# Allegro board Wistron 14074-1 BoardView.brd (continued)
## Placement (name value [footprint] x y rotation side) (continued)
PC4917  SC18P50V2JN-1-LL-GP  [C402H22]  141.88 16.32 180 bottom
PC4918  SC4D7U6D3V3KX-GP  [C603H36]  138.76 15.94 180 bottom
PC4919  SC4D7U25V5KX-GP  [C805H54]  140.26 32.66 180 bottom
PC4920  SC4D7U25V5KX-GP  [C805H54]  131.85 36.37 90 bottom
PC4921  SCD1U25V3KX-GP  [C603H36]  135.13 25.07 0 bottom
PC4922  SCD01U50V2KX-1GP  [C402H22]  131.91 39.83 90 bottom
PC4923  SCD01U50V2KX-1GP  [C402H22]  131.85 38.38 90 bottom
PC4924  SC4D7U25V5KX-GP  [C805H54]  142.24 32.66 180 bottom
PC4925  SCD01U50V2KX-1GP  [C402H22]  138.81 32.51 180 bottom
PC4926  SC1U10V2KX-1GP  [C402H22]  141.35 24.77 0 bottom
PC4927  SCD1U25V3KX-GP  [C603H36]  134.89 21.77 90 bottom
PC5001  SC1500P50V3KX-GP  [C603]  90.68 10.54 0 top
PC5002  SCD01U50V2KX-1GP  [C402H22]  71.26 11.73 270 top
PC5003  SCD1U16V2KX-3GP  [C402H22]  72.13 5.71 270 top
PC5004  SCD1U25V3KX-GP  [C603H36]  79.4 9.03 180 top
PC5005  SC1KP50V2KX-1GP  [C402H22]  72.75 11.29 180 top
PC5006  SCD01U16V2KX-3LLGP  [C402H22]  72.25 7.72 270 top
PC5007  SC4D7U25V5KX-GP  [C805H54]  80.59 4.75 270 top
PC5008  SCD22U25V3KX-GP  [C603H40]  71.55 13.57 180 top
PC5009  SC1U16V3KX-2GP  [C603H36]  75.71 13.11 90 top
PC5010  SC1U16V3KX-2GP  [C603H36]  108.56 11.42 180 top
PC5011  SCD1U50V3KX-GP  [C603H36]  90.65 6.62 180 top
PC5012  SC4D7U25V5KX-GP  [C805H54]  80.7 2.79 270 top
PC5028  SC1U10V2KX-1GP  [C402H22]  173.08 26.84 0 top
PC5029  SCD1U16V2KX-3GP  [C402H22]  170.56 28.45 270 bottom
PC5030  SCD033U16V2KX-GP  [C402H22]  177.16 23.6 0 top
PC5031  SC10U6D3V3MX-GP  [C603H38]  176.03 23.97 0 top
PC5032  SCD1U16V2KX-3GP  [C402H22]  181.08 23.85 180 top
PC5033  SC10U6D3V3KX-GP  [C603H38]  174.84 23.97 0 top
PC5034  SC1U10V2KX-1GP  [C402H22]  179.22 32.31 270 top
PC5035  SC1U10V2KX-1GP  [C402H22]  174.22 33.19 180 top
PC5036  SCD1U10V2KX-5GP  [C402H22]  181.86 30.33 90 top
PC5037  SCD1U10V2KX-5GP  [C402H22]  180.61 27.5 0 top
PC5038  SC10U25V5KX-GP  [C805H56]  177.29 34.65 90 top
PC5039  SC10U25V5KX-GP  [C805H56]  177.29 34.67 270 bottom
PC5040  SCD1U50V3KX-GP  [C603H36]  173.33 30.58 270 top
PC5041  SC1KP50V2KX-1GP  [C402H22]  177.64 36.61 0 top
PC5101  SC10U25V5KX-GP  [C805H56]  65.53 113.39 180 bottom
PC5102  SC10U25V5KX-GP  [C805H56]  63.35 112.95 90 top
PC5103  SCD1U16V2KX-3GP  [C402H22]  57.81 101.32 90 bottom
PC5104  SC1U10V2KX-1GP  [C402H22]  70.48 101.09 90 top
PC5105  SCD1U50V3KX-GP  [C603H36]  70.87 103.25 90 top
PC5106  SC1KP50V3KX-GP  [C603H36]  65.28 111.38 270 top
PC5107  SC22P50V2JN-4GP  [C402H22]  61.09 99.8 90 bottom
PC5108  SC10U6D3V3MX-GP  [C603H38]  78.11 101.45 270 top
PC5109  SCD1U16V2KX-3GP  [C402H22]  62.53 98.65 180 bottom
PC5110  SC1U6D3V2KX-GP  [C402H22]  24 85.72 90 top
PC5111  SC1U6D3V2KX-GP  [C402H22]  21.97 85.72 270 top
PC5112  SC1U10V2KX-1GP  [C402H22]  116.46 11.84 90 bottom
PC5211  SCD1U10V2KX-4GP  [C402H20]  90.7 137.79 225 top
PC5212  SCD1U16V2KX-3GP  [C402H22]  97.15 138.35 135 top
PC5213  SC1U10V2KX-1GP  [C402H22]  91.49 138.66 225 top
PC5214  SC10U6D3V3MX-GP  [C603H38]  98.04 137.69 135 top
PC5215  SC22P50V2JN-4GP  [C402H22]  98.25 131.1 315 top
PC5216  SC10U6D3V3MX-GP  [C603H38]  99.51 129.31 315 top
PC5217  SC10U6D3V3MX-GP  [C603H38]  99.57 135.9 135 top
PC5218  SCD1U16V2KX-3GP  [C402H22]  100.11 134.82 135 top
PC5219  SCD1U16V2KX-3GP  [C402H22]  60.99 102.21 90 bottom
PC5220  SCD1U10V2KX-4GP  [C402H20]  51.56 47.88 0 top
PC5221  SCD1U10V2KX-4GP  [C402H20]  90.17 133.93 225 top
PC5222  SCD1U10V2KX-4GP  [C402H20]  25.02 88.14 0 top
PCIE16  PCISLT164-28-GP  [2EG38217-D2D-4F]  16.14 113 90 top
PD5001  RB551V30-GP  [SOD323AKH38]  72.8 3.17 90 top
PG4401  GAP-CLOSE  [CON2C]  112.66 121.65 90 top
PG4402  GAP-CLOSE  [CON2C]  115.74 121.53 270 top
PG4501  GAP-CLOSE  [CON2C]  62.87 72.14 90 top
PG4502  GAP-CLOSE  [CON2C]  65.79 72.14 270 top
PG4901  GAP-CLOSE-PWR-3-GP  [GAP-CLOSE-PWR-3]  140.34 24.77 90 bottom
PG4902  GAP-CLOSE-PWR-3-GP  [GAP-CLOSE-PWR-3]  130.07 9.3 90 top
PG4903  GAP-CLOSE-PWR-3-GP  [GAP-CLOSE-PWR-3]  163.58 28.32 270 top
PG4904  GAP-CLOSE-PWR-3-GP  [GAP-CLOSE-PWR-3]  142.24 24.51 90 bottom
PL4401  IND-D33UH-12-GP-U  [L686647-127318H119]  114.19 121.97 90 top
PL4402  MHC1608S800QBP-GP  [L603H38]  106.05 136.27 0 top
PL4403  MHC1608S800QBP-GP  [L603H38]  106.82 139.32 90 top
PL4501  IND-D33UH-12-GP-U  [L686647-127318H119]  64.27 72.02 90 top
PL4502  MHC1608S800QBP-GP  [L603H38]  36.21 53.47 90 top
PL4601  MHC1608S800QBP-GP  [L603H38]  36.21 54.66 90 top
PL4701  IND-D82UH-19-GP-U  [L686647-127318H119]  90.18 116.58 315 top
PL4702  MHC1608S800QBP-GP  [L603H38]  73.33 130.89 270.3 top
PL4703  MHC1608S800QBP-GP  [L603H38]  83.95 131.32 135 top
PL4801  MHC1608S800QBP-GP  [L603H38]  168.15 33.51 0 top
PL4901  MHC1608S800QBP-GP  [L603H38]  140.26 36.24 180 bottom
PL4902  MHC1608S800QBP-GP  [L603H38]  142.24 36.24 180 bottom
PL4903  IND-3D3UH-116-GP-U  [L686647-127318H119]  129.39 25.77 0 bottom
PL4904  IND-3D3UH-116-GP-U  [L686647-127318H119]  152.91 30.1 270 bottom
PL5001  IND-D82UH-19-GP-U  [L686647-127318H119]  178.16 48.25 180 top
PL5002  MHC1608S800QBP-GP  [L603H38]  170.65 33.46 0 top
PL5003  MHC1608S800QBP-GP  [L603H38]  171.84 33.46 0 top
PL5004  MHC1608S800QBP-GP  [L603H38]  81.81 7.37 0 top
PL5005  IND-5D6UH-45-GP-U  [L686647-127318H119]  101.63 6.86 90 top
PL5006  MHC1608S800QBP-GP  [L603H38]  62.87 116.37 180 top
PL5007  MHC1608S800QBP-GP  [L603H38]  80.64 7.37 0 top
PL5101  IND-2D2UH-122-GP-U  [L686647-127318H119]  74.98 113.67 90 top
PL5102  MHC1608S800QBP-GP  [L603H38]  64.03 116.36 180 top
PL5103  MHC1608S800QBP-GP  [L603H38]  73.37 130.89 90 bottom
PN4401  NTC-100K-20-GP  [NTC-402H24-U]  120.4 131.14 180 top
PN4402  NTC-100K-20-GP  [NTC-402H24-U]  119.33 124.13 0 top
PN4501  NTC-100K-20-GP  [NTC-402H24-U]  51.69 78.11 90 top
PN4502  NTC-100K-20-GP  [NTC-402H24-U]  63.53 76.53 90 top
PQ4401  AON6520-GP  [PPAK-8P-5262H40]  107.81 130.87 0 top
PQ4402  AON6510-GP  [PPAK-8P-5262H40]  116.51 129.21 180 top
PQ4501  AON6520-GP  [PPAK-8P-5262H40]  54.61 65.7 90 top
PQ4502  AON6510-GP  [PPAK-8P-5262H40]  56.48 74.21 270 top
PQ4701  AON6520-GP  [PPAK-8P-5262H40]  87.48 126.4 45 top
PQ4702  AON6510-GP  [PPAK-8P-5262H40]  84.09 120.5 225 top
PQ4901  SM3319NSQGC-TRG-GP  [PPAK-8P-3030H40]  145.13 34.8 270 bottom
PQ4902  SM3317NSQGC-TRG-GP  [PPAK-8P-3030H40]  146.44 27.58 90 bottom
PQ4903  SM3319NSQGC-TRG-GP  [PPAK-8P-3030H40]  135.48 33.55 180 bottom
PQ4904  SM3317NSQGC-TRG-GP  [PPAK-8P-3030H40]  128.37 32.16 0 bottom
PQ5001  AON6520-GP  [PPAK-8P-5262H40]  173.38 38.82 180 top
PQ5002  AON6510-GP  [PPAK-8P-5262H40]  181.9 40.55 0 top
PQ5003  SM3319NSQGC-TRG-GP  [PPAK-8P-3030H40]  93.85 3.94 90 top
PQ5004  SM3317NSQGC-TRG-GP  [PPAK-8P-3030H40]  95.25 8.61 270 top
PQ5005  2N7002KDW-1-GP  [SOT-363H44]  80.49 16.21 270 top
PQ5101  SM3319NSQAC-TRG-GP  [PPAK-8P-3232H40]  67.05 115.24 90 top
PQ5102  SM3319NSQAC-TRG-GP  [PPAK-8P-3232H40]  68.47 108.54 270 top
PR3601  124R2F-U-GP  [R402H16]  119.91 11.84 90 bottom
PR3602  210R2F-L-GP  [R402H16]  115.37 12.88 90 bottom
PR4201  30KR2F-GP  [R402H16]  186.31 80.19 90 bottom
PR4202  390R2F-2GP  [R402H16]  189.38 91.67 0 bottom
PR4203  8K2R2F-1-GP  [R402H16]  188.34 91.72 0 bottom
PR4204  300KR2F-GP  [R402H16]  186.31 81.23 90 bottom
PR4205  30KR2F-GP  [R402H16]  190.88 90.07 90 bottom
PR4206  300KR2F-GP  [R402H16]  190.93 91.19 90 bottom
PR4207  15KR2F-GP  [R402H16]  188.72 93.22 90 bottom
PR4208  15KR2F-GP  [R402H16]  182.32 91.87 0 bottom
PR4209  100KR2F-L1-GP  [R402H16]  180.42 86.28 270 bottom
PR4210  15KR2F-GP  [R402H16]  182.78 93.34 270 bottom
PR4211  20KR2J-L2-GP  [R402H16]  190.47 80.04 0 bottom
PR4212  20KR2J-L2-GP  [R402H16]  189.41 80.04 0 bottom
PR4213  100KR2F-L1-GP  [R402H16]  180.39 87.33 90 bottom
PR4214  200KR2F-L-GP  [R402H16]  187.81 151.16 180 top
PR4215  100KR2J-1-GP  [R402H16]  187.37 149.58 270 top
PR4216  0R2J-2-GP  [R402H16]  190.88 92.23 90 bottom
PR4217  D1R2512F-3-GP-U  [R2512-1U1H36]  185.57 76.21 90 bottom
PR4218  300KR2F-GP  [R402H16]  184.4 81.23 90 bottom
PR4219  30KR2F-GP  [R402H16]  184.4 79.3 270 bottom
PR4220  0R5J-5-GP  [R805H24]  188.47 71.72 180 bottom
PR4221  0R5J-5-GP  [R805H24]  190.42 71.7 180 bottom
PR4222  0R2J-2-GP  [R402H16]  184.78 92.33 90 bottom
PR4223  15KR2F-GP  [R402H16]  186.82 93.24 270 bottom
PR4224  0R5J-5-GP  [R805H24]  192.38 71.7 180 bottom
PR4225  0R0402-PAD-2-GP  [0R0402-PAD-1]  184.78 91.26 90 bottom
PR4226  0R5J-5-GP  [R805H24]  194.36 71.7 180 bottom
PR4401  1KR2J-1-GP  [R402H16]  128.04 138.76 270 top
PR4404  47R2F-GP  [R402H16]  137.29 132.08 90 bottom
PR4405  1KR2F-3-GP  [R402H16]  136.88 131.85 180 top
PR4406  560KR2F-GP  [R402H16]  139.04 131.85 180 top
PR4407  3K3R2F-2-GP  [R402H16]  138.4 130.2 270 top
PR4408  100R2J-2-GP  [R402H14]  140.44 134.87 180 bottom
PR4409  100R2J-2-GP  [R402H14]  140.46 133.35 270 top
PR4410  0R0402-PAD-2-GP  [0R0402-PAD-1]  138.53 135.51 90 top
PR4411  1K5R2F-2-GP  [R402H16]  138.53 134.37 90 top
PR4413  0R0402-PAD-2-GP  [0R0402-PAD-1]  126.9 132.61 270 top
PR4414  62KR2F-GP  [R402H16]  125.45 132.18 0 top
PR4415  34KR2F-GP  [R402H16]  131.83 130.43 0 bottom
PR4416  10R2J-2-GP  [R402H14]  129.29 127.38 180 top
PR4417  100KR3F-GP  [R603H22]  130.43 126.85 180 top
PR4418  4K7R2F-GP  [R402H16]  137.16 128.22 270 top
PR4419  75KR2F-GP  [R402H16]  134.32 127.81 90 top
PR4420  150KR2F-L-GP  [R402H16]  132.74 127.25 180 top
PR4421  2D2R5J-1-GP  [R805H24]  112.19 127.81 180 top
PR4422  10KR2J-3-GP  [R402H16]  112.14 128.02 180 bottom
PR4423  0R5J-5-GP  [R805H24]  112.14 130.81 0 bottom
PR4424  2D2R5J-1-GP  [R805H24]  126.47 135.25 90 top
PR4426  54D9R2F-L1-GP  [R402H16]  131.29 138.68 270 top
PR4427  75R2F-2-GP  [R402H16]  131.93 137.16 0 top
PR4428  1R3J-L1-GP  [R603H22]  124.59 129.64 90 top
PR4429  1KR2J-1-GP  [R402H16]  125.6 137.24 0 top
PR4430  2D2R5J-1-GP  [R805H24]  138.91 138.43 270 top
PR4431  0R2J-2-GP  [R402H16]  125.55 130.73 270 top
PR4432  22KR2F-GP  [R402H16]  127.36 127.38 0 top
PR4433  18K7R2F-GP  [R402H16]  134.24 131.06 90 bottom
PR4434  1KR2J-1-GP  [R402H16]  125.6 137.16 180 bottom
PR4501  1KR2J-1-GP  [R402H16]  41.61 70.08 180 top
PR4504  47R2F-GP  [R402H16]  33.71 74.8 90 top
PR4505  1KR2F-3-GP  [R402H16]  33.71 75.84 90 top
PR4506  560KR2F-GP  [R402H16]  33.15 78.23 0 bottom
PR4507  3K3R2F-2-GP  [R402H16]  33.2 78.26 0 top
PR4510  0R0402-PAD-2-GP  [0R0402-PAD-1]  33.32 70.92 90 top
PR4511  1K5R2F-2-GP  [R402H16]  33.71 72.87 270 top
PR4513  0R0402-PAD-2-GP  [0R0402-PAD-1]  43.69 78.23 90 top
PR4514  62KR2F-GP  [R402H16]  45.59 78.23 90 top
PR4515  30KR2F-GP  [R402H16]  37.39 79.71 90 top
PR4516  10R2J-2-GP  [R402H14]  40.18 81.31 0 top
PR4517  100KR3F-GP  [R603H22]  40.18 83.59 0 top
PR4518  10KR2F-2-GP  [R402H16]  36.7 81.28 270 top
PR4519  75KR2F-GP  [R402H16]  38 82.93 0 top
PR4520  150KR2F-L-GP  [R402H16]  39.04 82.93 180 top
PR4521  2D2R5J-1-GP  [R805H24]  56.91 69.98 270 top
PR4522  10KR2J-3-GP  [R402H16]  46.1 75.82 0 top
PR4523  0R5J-5-GP  [R805H24]  43.81 74.4 270 top
PR4524  2D2R5J-1-GP  [R805H24]  43.84 72.34 270 top
PR4526  54D9R2F-L1-GP  [R402H16]  38.99 69.39 90 top
PR4527  75R2F-2-GP  [R402H16]  39.42 70.87 180 top
PR4528  1R3J-L1-GP  [R603H22]  44.75 82.58 0 top
PR4529  1KR2J-1-GP  [R402H16]  42.6 69.95 0 bottom
PR4530  2D2R5J-1-GP  [R805H24]  35.59 70.55 180 top
PR4531  48D7KR2F-GP  [R402H16]  43.69 79.38 90 top
PR4532  53K6R2F-GP  [R402H16]  42.29 81.28 180 top
PR4533  18K7R2F-GP  [R402H16]  33.66 79.76 270 top
PR4601  1KR2J-1-GP  [R402H16]  44.2 70.74 270 top
PR4701  5D1R2J-1-GP  [R402H16]  68.73 120.85 180 top
PR4702  470KR2F-GP  [R402H16]  69.47 124.71 0 top
PR4706  0R0603-PAD-2-GP-U  [0R0603-PAD-1-U]  94.33 113.28 45 top
PR4711  68KR2F-GP  [R402H16]  70.96 130.12 180 top
PR4712  2K2R2J-2-GP  [R402H16]  75.41 126.24 270 top
PR4713  2D2R5J-1-GP  [R805H24]  85.84 125.35 45 bottom
PR4714  2D2R5J-1-GP  [R805H24]  75.23 121.18 180 top
PR4715  10KR2J-3-GP  [R402H16]  92.18 123.39 135 top
PR4716  2D2R5J-1-GP  [R805H24]  93.84 121.81 45 top
PR4717  5K11R2F-L1-GP  [R402H16]  67.93 125.27 90 top
PR4718  10KR2F-2-GP  [R402H16]  67.94 126.31 270 top
PR4720  3K3R2J-3-GP  [R402H16]  59.46 100.99 0 bottom
PR4801  0R0805-PAD-2-GP-U  [0R0805-PAD-1-U]  49.35 54.64 270 top
PR4802  0R0603-PAD-2-GP-U  [0R0603-PAD-1-U]  49.07 52.93 270 top
PR4803  10KR2F-2-GP  [R402H16]  60.66 50.98 0 top
PR4804  0R0805-PAD-2-GP-U  [0R0805-PAD-1-U]  61.09 56.57 180 top
PR4805  2K2R2J-2-GP  [R402H16]  48.67 51.21 0 top
PR4806  4K42R2F-GP  [R402H16]  60.66 53.01 0 top
PR4820  3K3R2J-3-GP  [R402H16]  49.12 48.77 90 top
PR4903  2D2R5J-1-GP  [R805H24]  145.26 19.41 270 bottom
PR4904  0R5J-5-GP  [R805H24]  134.75 32.51 0 top
PR4905  0R5J-5-GP  [R805H24]  145.92 32.38 0 top
PR4906  0R0805-PAD-2-GP-U  [0R0805-PAD-1-U]  124.28 10.74 90 top
PR4907  0R0805-PAD-2-GP-U  [0R0805-PAD-1-U]  160.05 24.92 270 bottom
PR4908  0R0805-PAD-2-GP-U  [0R0805-PAD-1-U]  124.28 8.81 90 top
PR4909  0R0805-PAD-2-GP-U  [0R0805-PAD-1-U]  160.07 30.89 270 bottom
PR4910  0R0805-PAD-2-GP-U  [0R0805-PAD-1-U]  124.28 6.88 90 top
PR4911  2D2R5J-1-GP  [R805H24]  131.8 32.34 0 bottom
PR4912  2D2R5J-1-GP  [R805H24]  146.25 31.55 90 bottom
PR4913  0R0805-PAD-2-GP-U  [0R0805-PAD-1-U]  160.07 26.9 270 bottom
PR4914  6K65R2F-GP  [R402H16]  136.65 16.33 0 bottom
PR4915  0R0805-PAD-2-GP-U  [0R0805-PAD-1-U]  160.07 28.91 270 bottom
PR4916  10KR2F-2-GP  [R402H16]  137.67 16.33 180 bottom
PR4917  21K5R2F-GP  [R402H16]  139.27 24.74 180 bottom
PR4918  68KR2F-GP  [R402H16]  140.89 16.33 180 bottom
PR4919  10KR2F-2-GP  [R402H16]  138.25 24.77 0 bottom
PR4920  15KR2F-GP  [R402H16]  144.96 17.43 0 bottom
PR4921  10KR2F-2-GP  [R402H16]  144.43 15.93 270 bottom
PR4922  100KR2J-1-GP  [R402H16]  135.54 18.62 270 bottom
PR4923  127KR2F-GP  [R402H16]  139.85 16.33 180 bottom
PR4924  130KR2F-GP  [R402H16]  142.85 16.3 180 bottom
PR4925  100KR2J-1-GP  [R402H16]  136.78 24.26 270 bottom
PR4926  2D2R5J-1-GP  [R805H24]  134.42 20.14 270 bottom
PR5001  2D2R5J-1-GP  [R805H24]  94.54 8.1 270 bottom
PR5002  16KR2F-GP  [R402H16]  79.25 11.38 180 top
PR5003  3K3R2F-2-GP  [R402H16]  72.69 13.21 180 top
PR5004  75R2F-2-GP  [R402H16]  69.77 11.23 180 top
PR5005  2K21R2F-GP  [R402H16]  71.25 10.79 90 top
PR5006  158R2F-GP  [R402H16]  72.31 9.73 270 top
PR5007  0R0805-PAD-2-GP-U  [0R0805-PAD-1-U]  114.07 11.53 180 top
PR5008  0R0805-PAD-2-GP-U  [0R0805-PAD-1-U]  112.12 11.53 180 top
PR5009  0R0805-PAD-2-GP-U  [0R0805-PAD-1-U]  110.16 11.53 180 top
PR5010  2D2R5J-1-GP  [R805H24]  76.99 4.72 90 top
PR5011  2D2R5J-1-GP  [R805H24]  93.8 11.79 270 top
PR5012  10KR2F-2-GP  [R402H16]  182.09 23.85 0 top
PR5013  2D2R5J-1-GP  [R805H24]  76.15 14.68 270 top
PR5014  4D7R5J-1-GP  [R805H24]  77.01 6.71 270 top
PR5015  10KR2J-3-GP  [R402H16]  72.11 4.75 90 top
PR5016  10KR2J-3-GP  [R402H16]  96.9 8.77 0 bottom
PR5017  158R2F-GP  [R402H16]  72.31 8.66 270 top
PR5018  2K21R2F-GP  [R402H16]  72.06 6.73 270 top
PR5023  8K87R2F-2-GP  [R402H16]  177.29 33.15 270 top
PR5024  5D1R2J-1-GP  [R402H16]  177.3 32.13 90 top
PR5025  0R0805-PAD-2-GP-U  [0R0805-PAD-1-U]  160.39 51.7 270 top
PR5026  0R0805-PAD-2-GP-U  [0R0805-PAD-1-U]  160.39 49.76 270 top
PR5027  0R0603-PAD-2-GP-U  [0R0603-PAD-1-U]  172.39 25.12 90 top
PR5028  0R0805-PAD-2-GP-U  [0R0805-PAD-1-U]  160.37 47.8 270 top
PR5029  2D2R5J-1-GP  [R805H24]  177.66 40.59 0 top
PR5030  2D2R3J-2-GP  [R603H22]  172.42 29.09 90 top
PR5031  620KR2F-GP  [R402H16]  181.89 31.32 270 top
PR5032  100KR2J-1-GP  [R402H16]  182.07 32.36 270 top
PR5033  0R0805-PAD-2-GP-U  [0R0805-PAD-1-U]  160.36 43.9 270 top
PR5034  0R0603-PAD-2-GP-U  [0R0603-PAD-1-U]  170.4 26.67 90 bottom
PR5035  0R0402-PAD-2-GP  [0R0402-PAD-1]  179 23.87 0 top
PR5036  0R0805-PAD-2-GP-U  [0R0805-PAD-1-U]  160.36 45.86 270 top
PR5037  2D2R5J-1-GP  [R805H24]  171.3 39.02 180 bottom
PR5038  0R0805-PAD-2-GP-U  [0R0805-PAD-1-U]  160.36 41.95 270 top
PR5041  8K06R2F-GP  [R402H16]  180.06 23.85 180 top
PR5101  15K8R2F-GP  [R402H16]  61.1 98.84 90 bottom
PR5102  10KR2F-2-GP  [R402H16]  61.1 97.82 270 bottom
PR5103  10KR2J-3-GP  [R402H16]  70.1 116.26 90 bottom
PR5104  5D1R2J-1-GP  [R402H16]  70.48 102.11 270 top
PR5105  2D2R5J-1-GP  [R805H24]  68.44 111.83 270 top
PR5106  2D2R5J-1-GP  [R805H24]  71.25 104.9 270 top
PR5107  196KR2F-GP  [R402H16]  60.99 103.23 90 bottom
PR5108  0R0603-PAD-2-GP-U  [0R0603-PAD-1-U]  23.7 83.91 180 top
PR5109  0R0603-PAD-2-GP-U  [0R0603-PAD-1-U]  22.3 83.78 0 top
PR5110  100KR2F-L1-GP  [R402H16]  25.02 90.68 180 top
PR5115  2K2R2J-2-GP  [R402H16]  57.76 100.23 90 bottom
PR5116  470KR2F-GP  [R402H16]  65.38 100.05 270 bottom
PR5117  2D2R5J-1-GP  [R805H24]  66.98 118.47 270 top
PR5120  3K3R2J-3-GP  [R402H16]  57.81 102.34 90 bottom
PR5209  0R0603-PAD-2-GP-U  [0R0603-PAD-1-U]  92.07 139.76 225 top
PR5210  0R0805-PAD-2-GP-U  [0R0805-PAD-1-U]  96.23 139.82 135 top
PR5211  10KR2F-2-GP  [R402H16]  96.77 129.69 315 top
PR5213  0R0805-PAD-2-GP-U  [0R0805-PAD-1-U]  101.37 130.81 45 top
PR5214  5K49R2F-GP  [R402H16]  98.97 130.38 315 top
PR5215  0R0603-PAD-2-GP-U  [0R0603-PAD-1-U]  87.43 106.38 45 top
PR5216  0R0603-PAD-2-GP-U  [0R0603-PAD-1-U]  88.41 107.35 45 top
PR5217  0R0603-PAD-2-GP-U  [0R0603-PAD-1-U]  89.39 108.34 45 top
PR5218  0R0603-PAD-2-GP-U  [0R0603-PAD-1-U]  90.38 109.33 45 top
PR5219  0R0603-PAD-2-GP-U  [0R0603-PAD-1-U]  91.37 110.32 45 top
PR5220  0R0603-PAD-2-GP-U  [0R0603-PAD-1-U]  92.36 111.31 45 top
PR5221  0R0603-PAD-2-GP-U  [0R0603-PAD-1-U]  93.34 112.29 45 top
PR5222  0R0603-PAD-2-GP-U  [0R0603-PAD-1-U]  84.05 105.4 45 top
PR5223  0R0603-PAD-2-GP-U  [0R0603-PAD-1-U]  83.06 104.42 45 top
PR5224  0R0603-PAD-2-GP-U  [0R0603-PAD-1-U]  81.09 102.44 45 top
PR5225  0R0603-PAD-2-GP-U  [0R0603-PAD-1-U]  82.08 103.43 45 top
PR5229  10KR2J-3-GP  [R402H16]  57.99 48.64 270 top
PR5231  2K2R2J-2-GP  [R402H16]  89.99 137.07 45 top
PR5232  10KR2J-3-GP  [R402H16]  182.63 26.85 180 top
PR5233  10KR2J-3-GP  [R402H16]  181.86 29.34 270 top
PR5234  10KR2J-3-GP  [R402H16]  181.99 28.3 270 top
PR5240  3K3R2J-3-GP  [R402H16]  89.2 136.32 225 top
PR9742  0R0402-PAD-2-GP  [0R0402-PAD-1]  134.21 139.45 180 top
PR9757  0R0402-PAD-2-GP  [0R0402-PAD-1]  134.34 137.41 0 top
PR9758  200R2J-L1-GP  [R402H16]  133.07 137.16 180 top
PR9759  200R2J-L1-GP  [R402H16]  38.4 70.87 0 top
PR9763  10KR2J-3-GP  [R402H16]  181.61 26.82 180 top
PR9764  100R2J-2-GP  [R402H14]  33.3 70.94 90 bottom
PR9765  100R2J-2-GP  [R402H14]  33.22 73.25 0 bottom
PR9766  100R2J-2-GP  [R402H14]  94.78 81.64 270 bottom
PT4401  E820U2D5VM-6-GP  [ECAP-100D6D3H375]  123.83 123.95 0 top
PT4402  E820U2D5VM-6-GP  [ECAP-100D6D3H375]  122.5 116.23 0 top
PT4403  E820U2D5VM-6-GP  [ECAP-100D6D3H375]  129.9 118.99 0 top
PT4491  E270U16VM-16-GP  [ECAP-138D8-UH355]  118.75 139.95 0 top
PT4501  E820U2D5VM-6-GP  [ECAP-100D6D3H375]  81.25 81.13 90 top
PT4502  E820U2D5VM-6-GP  [ECAP-100D6D3H375]  72.54 76.99 0 top
PT4503  E820U2D5VM-6-GP  [ECAP-100D6D3H375]  72.75 69.11 0 top
PT4504  E820U2D5VM-6-GP  [ECAP-100D6D3H375]  79.55 73.46 0 top
PT4591  E270U16VM-16-GP  [ECAP-138D8-UH355]  42.42 52.98 0 top
PT4701  E820U2D5VM-6-GP  [ECAP-100D6D3H375]  83.52 111.28 90 top
PT4702  E560U6D3VM-3-GP  [ECAP-100D6D3H375]  78.59 130.3 0 top
PT4901  ST15U25VDM-7-GP  [CT7343H83]  139.7 32.03 0 top
PT4902  SE220U6D3VM-30-GP  [SE361416H178]  130.05 8.64 0 top
PT4903  SE220U6D3VM-30-GP  [SE361416H178]  163.55 27.67 0 top
PT5001  E820U2D5VM-6-GP  [ECAP-100D6D3H375]  170.43 50.4 90 top
PT5002  E820U2D5VM-6-GP  [ECAP-100D6D3H375]  166.13 43.85 90 top
PT5003  E560U6D3VM-3-GP  [ECAP-100D6D3H375]  163.9 36.34 0 top
PT5004  SE47U25VM-13-GP  [SE361414H241]  86.23 8.51 180 top
PT5005  E100U16VM-108-GP-U  [ECAP-100D6D3H237]  110.14 5.82 90 top
PT5101  E560U6D3VM-3-GP  [ECAP-100D6D3H375]  60.48 108.05 89.7 top
PT5102  E820U2D5VM-6-GP  [ECAP-100D6D3H375]  77.04 105.97 90 top
PU3601  UZ1085G-ADJ-TN3-R-1-GP-U  [SMD-TO-252-4H100]  118.11 16.18 90 bottom
PU4201  AO4407AL-GP  [SOIC8H69]  193.12 148.59 180 top
PU4202  LM358DR2G-GP  [SOIC8H69]  184.45 85.42 0 bottom
PU4203  LM358DR2G-GP  [SOIC8H69]  190.12 85.37 0 bottom
PU4401  NCP81201MNTXG-GP-U2  [LFQFN28J4-G2D7-UH40]  132.44 131.84 0 top
PU4501  NCP81201MNTXG-GP-U2  [LFQFN28J4-G2D7-UH40]  38.53 75.32 180 top
PU4701  RT8237CZQW-2-GP  [DFN10G3-G265175H32]  72.24 125.37 0 top
PU4801  APL5930KAI-TRG-1-GP  [SOIC8-G3530H63]  55.07 52.19 90 top
PU4902  RT8243BZQW-GP  [QFN20-G1D75H32]  139.85 20.53 0 bottom
PU5001  NCP1589AMNTWG-GP-U2  [LFDFN10G3-G2619H40]  75.78 10.26 270 top
PU5004  RT8207MZQW-GP-U  [QFN20-G1D75H32]  177.21 28.36 180 top
PU5101  RT8237CZQW-2-GP  [DFN10G3-G265175H32]  65.91 102.74 90 top
PU5102  S-1339D15-M5001-GP  [SOT-23-5H52]  22.61 91.44 0 top
PU5202  APL5930KAI-TRG-1-GP  [SOIC8-G3530H63]  94.96 134.23 45 top
Q1906  LMBT3904LT1G-GP  [SOT23CBE2D4H44]  33.66 137.87 180 top
Q2001  2N7002H-GP  [SOT23DGS2D4H44]  92.44 24.81 180 bottom
Q2501  MMBT3906-4-GP  [SOT23CBE2D4H44]  187.66 40.01 180 top
Q2502  MMBT3906-4-GP  [SOT23CBE2D4H44]  185.57 45.82 270 top
Q2503  LMBT3904LT1G-GP  [SOT23CBE2D4H44]  185.6 50.44 90 top
Q2701  MMDT3904-7-F-1-GP  [SOT-363H44]  33.3 151.23 270 top
Q2702  MMDT3904-7-F-1-GP  [SOT-363H44]  16.86 138.05 180 bottom
Q2703  MMDT3904-7-F-1-GP  [SOT-363H44]  16.82 134 0 bottom
Q2704  MMDT3904-7-F-1-GP  [SOT-363H44]  50.57 141.76 270 top
Q2705  MMDT3904-7-F-1-GP  [SOT-363H44]  42.9 142.78 270 top
Q2706  MMBT3906-4-GP  [SOT23CBE2D4H44]  26.34 139.73 270 top
Q2707  MMBT3906-4-GP  [SOT23CBE2D4H44]  16.87 144.41 90 top
Q2709  MMBT3906-4-GP  [SOT23CBE2D4H44]  24.43 144.42 270 top
Q2711  MMBT3904-4-GP  [SOT23CBE2D4H44]  37.54 115.11 90 bottom
Q2712  MMBT3904-4-GP  [SOT23CBE2D4H44]  20.65 144.41 90 top
Q3401  MMBT3906-4-GP  [SOT23CBE2D4H44]  12.37 18.49 0 bottom
Q3402  MMBT3904-4-GP  [SOT23CBE2D4H44]  177.77 18.67 90 bottom
Q3403  2N7002H-GP  [SOT23DGS2D4H44]  8.69 31.11 180 bottom
Q3404  MMBT3906-4-GP  [SOT23CBE2D4H44]  12.45 31.06 0 bottom
Q3409  2N7002KDW-1-GP  [SOT-363H44]  7.57 12.78 270 top
Q3507  QM3004D-GP  [SMD-TO-252-DGS6698H99]  191.26 22.71 180 top
Q3508  AO3413L-GP  [SOT23DGS2D8H50]  181.86 15.19 180 top
Q3509  AO3413L-GP  [SOT23DGS2D8H50]  184.23 19 270 top
Q3510  AO3413L-GP  [SOT23DGS2D8H50]  6.63 98.15 90 bottom
Q3511  AO3413L-GP  [SOT23DGS2D8H50]  6.63 102.34 90 bottom
Q3512  2N7002H-GP  [SOT23DGS2D4H44]  160.53 19.18 0 bottom
Q3514  2N7002H-GP  [SOT23DGS2D4H44]  156.97 18.34 180 bottom
Q3516  2N7002H-GP  [SOT23DGS2D4H44]  156.84 22.05 90 bottom
Q4001  2N7002KDW-1-GP  [SOT-363H44]  99.3 36.63 180 bottom
Q4101  2N7002KDW-1-GP  [SOT-363H44]  6.55 17.07 90 bottom
Q4201  2N7002A-7-GP  [SOT23DGS2D4H48]  179.86 79.28 0 bottom
Q4202  2N7002KDW-GP  [SOT-363H44]  179.96 83.95 180 bottom
Q4301  MMBT3906-4-GP  [SOT23CBE2D4H44]  171.93 17.91 0 bottom
Q4302  2N7002KDW-GP  [SOT-363H44]  179.07 89.66 0 bottom
Q4303  2N7002KDW-1-GP  [SOT-363H44]  151.43 22.05 180 bottom
Q4304  2N7002H-GP  [SOT23DGS2D4H44]  179.87 75.51 180 bottom
Q5401  2N7002A-7-GP  [SOT23DGS2D4H48]  164.34 20.24 0 bottom
Q6502  2N7002H-GP  [SOT23DGS2D4H44]  158.19 157.15 0 top
Q6503  2N7002H-GP  [SOT23DGS2D4H44]  135.31 154.13 270 top
Q6504  LMBT3904LT1G-GP  [SOT23CBE2D4H44]  16.33 23.72 90 bottom
Q6509  DMN5L06K-7-GP  [SOT23DGS2D4H48]  174.24 77.34 180 bottom
Q6510  2N7002H-GP  [SOT23DGS2D4H44]  175.4 64.75 90 bottom
Q6511  DMN5L06K-7-GP  [SOT23DGS2D4H48]  174.24 73.53 0 bottom
Q6512  2N7002H-GP  [SOT23DGS2D4H44]  174.24 69.6 180 bottom
Q6514  2N7002H-GP  [SOT23DGS2D4H44]  157.61 144.53 90 top
Q6515  DMN5L06K-7-GP  [SOT23DGS2D4H48]  155.45 150.75 90 top
Q6516  DMN5L06K-7-GP  [SOT23DGS2D4H48]  160.12 153.34 0 top
Q6517  DMN5L06K-7-GP  [SOT23DGS2D4H48]  127.44 149.96 180 top
Q6518  DMN5L06K-7-GP  [SOT23DGS2D4H48]  131.52 152.46 270 top
Q6519  2N7002H-GP  [SOT23DGS2D4H44]  131.11 148.77 180 top
Q6520  2N7002H-GP  [SOT23DGS2D4H44]  181.1 141.35 90 top
Q6527  2N7002H-GP  [SOT23DGS2D4H44]  7.32 90.42 180 bottom
Q6528  2N7002KDW-1-GP  [SOT-363H44]  63.39 125.11 180 bottom
Q6530  MMDT3904-7-F-1-GP  [SOT-363H44]  5.71 64.52 0 bottom
Q6531  MMDT3904-7-F-1-GP  [SOT-363H44]  6.1 54.53 0 bottom
Q6532  LMBT3904LT1G-GP  [SOT23CBE2D4H44]  184.12 66.9 180 bottom
Q6533  MMDT3904-7-F-1-GP  [SOT-363H44]  187.43 66.9 0 bottom
Q6539  LMBT3904LT1G-GP  [SOT23CBE2D4H44]  77.34 39.62 0 top
Q6540  MMDT3904-7-F-1-GP  [SOT-363H44]  6.43 112.52 0 bottom
Q6541  MMDT3904-7-F-1-GP  [SOT-363H44]  5.61 59.26 0 bottom
Q6542  2N7002KDW-1-GP  [SOT-363H44]  181.53 148.84 180 bottom
Q6543  2N7002KDW-1-GP  [SOT-363H44]  184.58 148.84 180 bottom
Q6544  2N7002H-GP  [SOT23DGS2D4H44]  7.11 118.75 270 bottom
Q6545  AO3413L-GP  [SOT23DGS2D8H50]  7.11 122.43 90 bottom
Q6546  LMBT3904LT1G-GP  [SOT23CBE2D4H44]  27.51 80.21 180 top
Q6547  LMBT3904LT1G-GP  [SOT23CBE2D4H44]  5.87 107.06 0 top
Q6548  LMBT3904LT1G-GP  [SOT23CBE2D4H44]  31.22 84.18 270 top
Q6549  LMBT3904LT1G-GP  [SOT23CBE2D4H44]  44.2 125.02 270 bottom
Q6550  2N7002H-GP  [SOT23DGS2D4H44]  11.46 22.56 0 bottom
Q6551  LMBT3904LT1G-GP  [SOT23CBE2D4H44]  7.37 68.58 180 bottom
Q6552  LMBT3904LT1G-GP  [SOT23CBE2D4H44]  153.03 129.57 90 top
Q6553  LMBT3904LT1G-GP  [SOT23CBE2D4H44]  178.21 146.51 180 bottom
R1  2KR2J-1-GP  [R402H16]  154.56 153.03 270 top
R2  2KR2J-1-GP  [R402H16]  156.95 153.57 0 top
R501  182R2F-GP  [R402H16]  119.89 84.2 225 bottom
R502  182R2F-GP  [R402H16]  118.52 85.72 45 bottom
R503  4K7R2F-GP  [R402H16]  131.36 72.64 135 top
R504  4K7R2F-GP  [R402H16]  130.54 73.68 135 top
R505  4K7R2F-GP  [R402H16]  134.88 70.31 135 top
R506  4K7R2F-GP  [R402H16]  138.49 68.26 135 top
R507  0R2J-2-GP  [R402H16]  134.14 71.83 225 top
R508  0R2J-2-GP  [R402H16]  128.44 75.16 45 top
R509  0R2J-2-GP  [R402H16]  137.19 69.06 225 top
R510  0R2J-2-GP  [R402H16]  140.64 68.58 225 top
R511  4K7R2F-GP  [R402H16]  132.1 71.9 315 top
R512  4K7R2F-GP  [R402H16]  129.81 74.4 315 top
R513  4K7R2F-GP  [R402H16]  135.6 69.58 315 top
R514  4K7R2F-GP  [R402H16]  139.23 67.54 315 top
R801  402R2F-GP  [R402H16]  110.87 100.33 45 bottom
R802  402R2F-GP  [R402H16]  116.18 106.02 0 bottom
R804  100R2F-L1-GP-U  [R402H14]  105.58 87.29 135 bottom
R809  80D6R2F-L-GP  [R402H16]  103.99 87.38 180 bottom
R1201  10KR2J-3-GP  [R402H16]  149.22 47.88 180 bottom
R1202  4K7R2F-GP  [R402H16]  122.73 38.07 270 bottom
R1203  4K7R2F-GP  [R402H16]  93.65 41 90 bottom
R1204  10KR2J-3-GP  [R402H16]  149.1 42.04 180 bottom
R1205  10KR2J-3-GP  [R402H16]  148.08 42.04 180 bottom
R1206  0R0402-PAD-2-GP  [0R0402-PAD-1]  125.22 38.07 90 bottom
R1207  0R0402-PAD-2-GP  [0R0402-PAD-1]  91.95 40.64 180 bottom
R1208  10KR2J-3-GP  [R402H16]  150.62 41.53 270 bottom
R1209  10KR2J-3-GP  [R402H16]  146.62 42.12 90 bottom
R1210  4K7R2F-GP  [R402H16]  122.73 39.12 90 bottom
R1211  4K7R2F-GP  [R402H16]  93.65 39.98 270 bottom
R1216  0R0402-PAD-2-GP  [0R0402-PAD-1]  96.79 40.31 90 bottom
R1226  2K2R2J-2-GP  [R402H16]  176.4 67.06 90 bottom
R1301  10KR2J-3-GP  [R402H16]  174.47 61.82 0 bottom
R1302  10KR2J-3-GP  [R402H16]  175.51 61.82 180 bottom
R1303  10KR2J-3-GP  [R402H16]  173.23 61.85 0 bottom
R1304  4K7R2F-GP  [R402H16]  173.06 83.83 180 bottom
R1305  4K7R2F-GP  [R402H16]  166.55 128.3 90 bottom
R1306  0R0402-PAD-2-GP  [0R0402-PAD-1]  173.35 81.41 0 bottom
R1307  0R0402-PAD-2-GP  [0R0402-PAD-1]  164.06 128.24 270 bottom
R1308  10KR2J-3-GP  [R402H16]  176.53 61.82 0 bottom
R1309  10KR2J-3-GP  [R402H16]  172.21 61.85 180 bottom
R1310  4K7R2F-GP  [R402H16]  174.12 83.83 0 bottom
R1311  4K7R2F-GP  [R402H16]  166.55 127.28 270 bottom
R1316  0R0402-PAD-2-GP  [0R0402-PAD-1]  168.78 125.22 90 bottom
R1501  4K7R2F-GP  [R402H16]  148.77 133.12 270 top
R1502  4K7R2F-GP  [R402H16]  132.87 108.41 315 top
R1503  10KR2F-2-GP  [R402H16]  148.48 122.08 225 bottom
R1504  10KR2F-2-GP  [R402H16]  135.07 108.98 135 top
R1505  100KR2J-1-GP  [R402H16]  172.87 119.89 270 top
R1507  10KR2F-2-GP  [R402H16]  157.88 128.62 0 top
R1508  10KR2F-2-GP  [R402H16]  149.88 130.6 0 top
R1509  10KR2F-2-GP  [R402H16]  149.61 132.08 90 top
R1510  10KR2F-2-GP  [R402H16]  148.66 130.57 0 top
R1511  10KR2F-2-GP  [R402H16]  133.67 107.6 315 top
R1512  10KR2F-2-GP  [R402H16]  191.34 97.61 0 bottom
R1513  10KR2F-2-GP  [R402H16]  190.63 119.41 180 bottom
R1515  10KR2J-3-GP  [R402H16]  33.5 122.28 90 top
R1516  10KR2F-2-GP  [R402H16]  148.76 134.16 90 top
R1517  10KR2F-2-GP  [R402H16]  131.39 106.94 315 top
R1518  10KR2F-2-GP  [R402H16]  147.72 121.31 45 bottom
R1519  10KR2F-2-GP  [R402H16]  134.37 109.73 135 top
R1520  10KR2F-2-GP  [R402H16]  172.89 118.74 90 top
R1522  10KR2F-2-GP  [R402H16]  156.82 128.62 180 top
R1523  10KR2F-2-GP  [R402H16]  149.91 128.65 0 top
R1524  4K7R2F-GP  [R402H16]  155.57 128.7 0 top
R1525  10KR2F-2-GP  [R402H16]  148.65 128.67 0 top
R1526  10KR2F-2-GP  [R402H16]  132.16 106.14 315 top
R1527  100KR2J-1-GP  [R402H16]  190.27 97.61 180 bottom
R1528  100KR2J-1-GP  [R402H16]  189 118.75 90 bottom
R1529  100KR2J-1-GP  [R402H16]  188.52 120.27 180 bottom
R1530  200KR2F-L-GP  [R402H16]  96.21 100.07 135 top
R1533  1KR2J-1-GP  [R402H16]  92.61 72.42 315 bottom
R1534  2K49R2F-GP  [R402H16]  108.3 93.25 135 bottom
R1535  49D9R2F-GP  [R402H16]  105.79 92.53 270 bottom
R1536  100R2F-L1-GP-U  [R402H14]  118.97 95.17 135 bottom
R1540  100KR2J-1-GP  [R402H16]  172.78 135.56 90 top
R1541  4K7R2F-GP  [R402H16]  172.9 132.03 270 top
R1542  0R2J-2-GP  [R402H16]  154.1 131.88 270 top
R1601  40K2R2F-GP  [R402H16]  102.58 148.86 0 top
R1602  10KR2F-2-GP  [R402H16]  103.66 149.02 180 top
R1603  0R2J-2-GP  [R402H16]  100.58 116.37 45 top
R1632  10KR2J-3-GP  [R402H16]  36.02 136.88 0 top
R1634  10KR2J-3-GP  [R402H16]  30.91 138.23 180 top
R1801  10KR2J-3-GP  [R402H16]  85.98 75.97 90 bottom
R1802  10KR2J-3-GP  [R402H16]  86.13 77.44 0 bottom
R1803  402R2F-GP  [R402H16]  111.25 96.52 225 bottom
R1804  0R0402-PAD-2-GP  [0R0402-PAD-1]  70.69 87.81 90 top
R1805  402R2F-GP  [R402H16]  104.14 97.13 0 bottom
R1806  0R0402-PAD-2-GP  [0R0402-PAD-1]  70.69 86.74 90 top
R1807  10KR2J-3-GP  [R402H16]  97.67 79.35 90 top
R1901  0R2J-2-GP  [R402H16]  28.75 84.15 0 top
R1902  33R2J-2-GP  [R402H16]  92.81 82.45 90 top
R1903  33R2J-2-GP  [R402H16]  92.86 83.49 90 top
R1904  0R2J-2-GP  [R402H16]  43.64 122.71 270 bottom
R1905  0R0402-PAD-2-GP  [0R0402-PAD-1]  46.74 123.34 180 bottom
R1906  0R2J-2-GP  [R402H16]  43.64 121.69 90 bottom
R1907  0R0402-PAD-2-GP  [0R0402-PAD-1]  43.18 127.74 180 bottom
R1908  0R2J-2-GP  [R402H16]  34.67 84.07 0 top
R1909  0R0402-PAD-2-GP  [0R0402-PAD-1]  33.63 84.07 0 top
R1910  33R2J-2-GP  [R402H16]  80.04 38.66 0 top
R1911  0R2J-2-GP  [R402H16]  89.88 102.1 225 top
R1912  100KR2J-1-GP  [R402H16]  93.42 92.08 0 bottom
R1915  1KR2J-1-GP  [R402H16]  94.82 75.79 315 top
R1917  10MR2J-L-GP  [R402H16]  93.62 94.11 135 top
R1918  20KR2J-L2-GP  [R402H16]  32.72 133.17 0 bottom
R1919  20KR2J-L2-GP  [R402H16]  53.19 111.63 180 bottom
R1920  1KR2J-1-GP  [R402H16]  77.6 42.04 270 top
R1930  20KR2J-L2-GP  [R402H16]  137.16 140.87 0 top
R1933  10KR2J-3-GP  [R402H16]  99.59 79.35 270 top
R1935  100R2F-L1-GP-U  [R402H14]  94.92 85.55 90 top
R1936  10KR2J-3-GP  [R402H16]  94.25 88.04 270 bottom
R1937  0R0402-PAD-2-GP  [0R0402-PAD-1]  138.28 140.84 180 top
R1938  51R2J-2-GP  [R402H16]  177.98 113.21 270 bottom
R1940  51R2J-2-GP  [R402H16]  190.38 111.58 90 bottom
R1942  51R2J-2-GP  [R402H16]  190.5 114.17 90 bottom
R1943  51R2J-2-GP  [R402H16]  190.5 112.9 90 bottom
R1944  51R2J-2-GP  [R402H16]  190.35 110.52 90 bottom
R1945  10KR2J-3-GP  [R402H16]  96.49 91.31 90 bottom
R2001  10KR2F-2-GP  [R402H16]  96.06 26.04 90 bottom
R2002  10KR2F-2-GP  [R402H16]  96.04 23.2 90 bottom
R2003  10KR2F-2-GP  [R402H16]  93.93 21.99 90 bottom
R2004  10KR2J-3-GP  [R402H16]  107.11 18.58 180 bottom
R2005  2KR2F-3-GP  [R402H16]  95.52 21.67 180 bottom
R2007  0R0402-PAD-2-GP  [0R0402-PAD-1]  106.01 20.75 180 bottom
R2008  15KR2F-GP  [R402H16]  95.73 19.48 90 bottom
R2010  10KR2F-2-GP  [R402H16]  98.9 22.33 270 bottom
R2011  33R2J-2-GP  [R402H16]  114.17 20.32 0 top
R2013  6K49R2F-1-GP  [R402H16]  99.69 19.33 90 bottom
R2014  10KR2F-2-GP  [R402H16]  99.71 20.4 90 bottom
R2015  0R0402-PAD-2-GP  [0R0402-PAD-1]  115.8 23.65 270 bottom
R2016  1KR2J-1-GP  [R402H16]  116.23 25.83 90 top
R2018  10KR2F-2-GP  [R402H16]  102.41 20.87 180 bottom
R2019  10KR2F-2-GP  [R402H16]  101.3 20.83 180 bottom
R2020  NTC-10K-19-GP-U  [NTC-402H22-U]  121.39 128.63 180 top
R2021  NTC-10K-19-GP-U  [NTC-402H22-U]  173.18 84.68 90 top
R2022  10KR2J-3-GP  [R402H16]  113.8 33.23 0 bottom
R2024  4K7R2J-2-GP  [R402H16]  98.51 33.21 90 bottom
R2025  10KR2J-3-GP  [R402H16]  106.22 36.73 0 bottom
R2026  0R2J-2-GP  [R402H16]  117.88 21.05 0 bottom
R2027  10KR2J-3-GP  [R402H16]  75.67 27.89 90 top
R2028  10KR2J-3-GP  [R402H16]  72.09 27.89 90 top
R2029  2K2R2J-2-GP  [R402H16]  115.31 30.87 90 bottom
R2030  8K2R2J-3-GP  [R402H16]  115.34 29.82 90 bottom
R2031  8K2R2J-3-GP  [R402H16]  98.53 30.1 270 bottom
R2032  8K2R2J-3-GP  [R402H16]  98.51 32.17 270 bottom
R2033  1KR2J-1-GP  [R402H16]  75.25 20.7 90 top
R2034  1KR2J-1-GP  [R402H16]  71.57 20.65 90 top
R2035  8K2R2J-3-GP  [R402H16]  98.53 29.06 270 bottom
R2036  10KR2J-3-GP  [R402H16]  112.9 35.89 180 bottom
R2037  10KR2J-3-GP  [R402H16]  107.26 36.73 180 bottom
R2038  1KR2J-1-GP  [R402H16]  104.17 35.59 0 bottom
R2041  10KR2J-3-GP  [R402H16]  116.41 21.69 90 top
R2042  4K7R2J-2-GP  [R402H16]  97.65 27.99 90 bottom
R2043  2K2R2J-2-GP  [R402H16]  111.48 20.68 270 top
R2045  10KR2J-3-GP  [R402H16]  119.66 20.68 90 top
R2046  4K7R2J-2-GP  [R402H16]  99.16 27.57 0 bottom
R2047  10KR2J-3-GP  [R402H16]  105.21 35.05 0 bottom
R2048  10KR2J-3-GP  [R402H16]  102.77 34.98 180 bottom
R2049  1KR2J-1-GP  [R402H16]  114.91 30.25 180 top
R2050  100R2J-2-GP  [R402H14]  114.55 26.13 270 bottom
R2051  10KR2J-3-GP  [R402H16]  116.64 20.65 90 top
R2054  10KR2F-2-GP  [R402H16]  116.95 29.27 0 bottom
R2056  330R2J-3-GP  [R402H16]  99.17 26.09 90 bottom
R2057  4K7R2J-2-GP  [R402H16]  99.31 34.29 270 bottom
R2101  0R0402-PAD-2-GP  [0R0402-PAD-1]  49.71 111.73 90 top
R2102  0R0402-PAD-2-GP  [0R0402-PAD-1]  21.46 117.67 0 top
R2103  0R0402-PAD-2-GP  [0R0402-PAD-1]  53.14 112.75 0 top
R2104  0R0402-PAD-2-GP  [0R0402-PAD-1]  22.61 117.73 0 top
R2105  300R2J-4-GP  [R402H16]  56.21 118.38 0 top
R2106  2K49R2F-GP  [R402H16]  56.32 121.2 270 top
R2107  0R5J-5-GP  [R805H24]  56.24 112.09 90 top
R2108  1KR2F-3-GP  [R402H16]  49.76 113.77 90 top
R2109  15KR2F-GP  [R402H16]  49.73 112.75 90 top
R2110  0R2J-2-GP  [R402H16]  45.67 119.42 180 top
R2112  10KR2J-3-GP  [R402H16]  45.69 121.39 180 top
R2113  10KR2J-3-GP  [R402H16]  46.58 121.84 270 bottom
R2114  10MR2J-L-GP  [R402H16]  55.94 119.93 90 top
R2115  0R2J-2-GP  [R402H16]  47.79 113.66 270 top
R2121  680R2F-GP  [R402H16]  57.25 118.46 180 top
R2130  0R2J-2-GP  [R402H16]  113.26 104.8 270 bottom
R2203  10KR2J-3-GP  [R402H16]  15.65 166.33 180 top
R2204  0R2J-2-GP  [R402H16]  11.99 163.13 270 top
R2205  5K1R2F-2-GP  [R402H16]  26.34 149.91 270 top
R2206  10KR2F-2-GP  [R402H16]  26.34 150.94 270 top
R2207  20KR2F-L-GP  [R402H16]  12 164.19 270 top
R2208  20KR2F-L-GP  [R402H16]  26.34 148.84 270 top
R2209  39K2R2F-L-GP  [R402H16]  11.99 162.09 270 top
R2213  20KR2F-L-GP  [R402H16]  11.25 155.96 0 top
R2214  4K7R2J-2-GP  [R402H16]  13.7 133.53 0 top
R2218  4K7R2J-2-GP  [R402H16]  13.65 135.46 0 top
R2220  1KR2J-1-GP  [R402H16]  26.82 151.99 90 top
R2221  1KR2J-1-GP  [R402H16]  28.79 151.98 90 top
R2222  75R2J-1-GP  [R402H16]  10.74 141.82 0 top
R2223  10KR2J-3-GP  [R402H16]  12.46 131.25 0 top
R2224  75R2J-1-GP  [R402H16]  11.9 141.82 0 top
R2225  0R0402-PAD-2-GP  [0R0402-PAD-1]  14.22 131.73 90 top
R2226  4K7R2J-2-GP  [R402H16]  13.65 137.51 0 top
R2228  0R0402-PAD-2-GP  [0R0402-PAD-1]  10.06 163.12 270 top
R2229  4K7R2J-2-GP  [R402H16]  13.65 139.41 0 top
R2230  22KR2J-GP  [R402H16]  13.04 141.83 180 top
R2231  22KR2J-GP  [R402H16]  9.66 141.83 180 top
R2412  0R2J-2-GP  [R402H16]  178.26 160.4 180 top
R2413  0R2J-2-GP  [R402H16]  184.24 158.44 180 top
R2414  4K7R2J-2-GP  [R402H16]  180.21 149.35 270 top
R2415  4K7R2J-2-GP  [R402H16]  180.21 148.21 270 top
R2418  150R2F-1-GP  [R402H16]  171.4 154.74 90 top
R2419  150R2F-1-GP  [R402H16]  173.43 154.74 90 top
R2420  150R2F-1-GP  [R402H16]  175.39 154.74 90 top
R2474  10KR2J-3-GP  [R402H16]  116.61 35.18 0 top
R2475  1KR2J-1-GP  [R402H16]  116 32.88 90 bottom
R2501  2K2R2J-2-GP  [R402H16]  188.04 47.88 0 top
R2508  10KR2J-3-GP  [R402H16]  186.97 42.93 180 top
R2509  0R3J-0-U-GP  [R603H22]  187.15 36.7 270 top
R2510  2K2R2J-2-GP  [R402H16]  191.77 51.31 90 top
R2511  4K7R2J-2-GP  [R402H16]  187.99 42.93 0 top
R2512  4K7R2J-2-GP  [R402H16]  184.61 48.13 270 top
R2513  100R2J-2-GP  [R402H14]  191.77 50.16 90 top
R2514  10KR2J-3-GP  [R402H16]  193.29 50.8 0 top
R2515  100KR2J-1-GP  [R402H16]  186.51 48.13 270 top
R2516  330R2F-GP  [R402H16]  189.05 47.88 0 top
R2517  4K7R2J-2-GP  [R402H16]  189.03 42.93 180 top
R2518  20KR2J-L2-GP  [R402H16]  189.05 44.83 180 top
R2519  0R0402-PAD-2-GP  [0R0402-PAD-1]  188.04 44.83 0 top
R2520  8K2R2J-3-GP  [R402H16]  188.54 46.35 90 top
R2522  0R0402-PAD-2-GP  [0R0402-PAD-1]  80.52 44.32 0 top
R2701  1KR2J-1-GP  [R402H16]  30.89 150.83 180 top
R2702  75R2J-1-GP  [R402H16]  53.85 144.04 270 top
R2703  75R2J-1-GP  [R402H16]  55.75 144.04 90 top
R2704  1KR2J-1-GP  [R402H16]  19.48 137.52 90 bottom
R2705  1KR2J-1-GP  [R402H16]  19.13 139.11 0 bottom
R2706  75R2J-1-GP  [R402H16]  42.06 146.05 90 top
R2707  75R2J-1-GP  [R402H16]  42.06 140.69 90 top
R2708  1KR2J-1-GP  [R402H16]  19.51 134.65 90 bottom
R2709  22KR2J-GP  [R402H16]  49.33 144.3 180 top
R2710  22KR2J-GP  [R402H16]  42.06 145.01 270 top
R2711  1KR2J-1-GP  [R402H16]  19.12 132.98 180 bottom
R2712  2K2R2J-2-GP  [R402H16]  37.5 151.85 0 top
R2713  75R2J-1-GP  [R402H16]  31.38 153.33 90 top
R2714  1KR2J-1-GP  [R402H16]  48.11 141.34 180 top
R2715  75R2J-1-GP  [R402H16]  41.39 148.95 90 top
R2716  1KR2J-1-GP  [R402H16]  53.62 141.44 180 top
R2717  2K2R2J-2-GP  [R402H16]  41.39 147.91 90 top
R2718  1KR2J-1-GP  [R402H16]  39.75 142.92 0 top
R2719  1KR2J-1-GP  [R402H16]  45.52 143.27 0 top
R2720  10KR2J-3-GP  [R402H16]  26.84 142.53 0 top
R2721  10KR2J-3-GP  [R402H16]  21.03 141.59 0 top
R2722  220KR2J-L2-GP  [R402H16]  23.49 140.54 0 top
R2723  1KR2J-1-GP  [R402H16]  36.62 150.37 90 top
R2725  1KR2J-1-GP  [R402H16]  23.79 147.48 0 top
R2726  1KR2J-1-GP  [R402H16]  23.82 149.38 0 top
R2729  75R3J-L-GP  [R603H22]  39.85 119 90 bottom
R2730  2K2R2J-2-GP  [R402H16]  35.1 114.2 0 bottom
R2731  75R3J-L-GP  [R603H22]  39.85 117.75 90 bottom
R2732  1KR2J-1-GP  [R402H16]  34.04 114.25 180 bottom
R2733  10KR2J-3-GP  [R402H16]  21.41 148.06 180 top
R2734  1KR2J-1-GP  [R402H16]  23.47 142.06 90 top
R2801  330R2J-3-GP  [R402H16]  60.12 143.71 270 top
R2810  330R2J-3-GP  [R402H16]  59.17 141.65 0 top
R2811  200R2J-L1-GP  [R402H16]  85.74 141.71 0 top
R2813  330R2J-3-GP  [R402H16]  60.2 141.64 0 top
R2814  330R2J-3-GP  [R402H16]  60.12 144.73 270 top
R2903  32K4R2F-1-GP  [R402H16]  101.5 148.86 0 top
R2904  32K4R2F-1-GP  [R402H16]  18.08 12.4 90 top
R2908  18K7R2F-GP  [R402H16]  102.44 146.94 0 top
R2910  18K7R2F-GP  [R402H16]  20.45 11.94 0 top
R3202  10KR2J-3-GP  [R402H16]  64.8 45.19 0 top
R3402  91R3J-GP  [R603H22]  15.11 28.57 90 bottom
R3403  10KR2J-3-GP  [R402H16]  178.92 21.46 270 top
R3404  0R0402-PAD-2-GP  [0R0402-PAD-1]  176.78 15.37 270 bottom
R3405  10KR2J-3-GP  [R402H16]  153.82 19.25 0 bottom
R3406  0R0402-PAD-2-GP  [0R0402-PAD-1]  31.65 14.12 270 top
R3407  10KR2J-3-GP  [R402H16]  149.86 16.08 0 bottom
R3409  10KR2J-3-GP  [R402H16]  119.37 20.68 90 bottom
R3410  33R2J-2-GP  [R402H16]  31.88 18.67 180 top
R3411  10KR2J-3-GP  [R402H16]  8.84 10.29 180 top
R3413  22KR2J-GP  [R402H16]  7.92 33.58 270 bottom
R3414  22KR2J-GP  [R402H16]  8.25 28.64 90 bottom
R3415  4K7R2J-2-GP  [R402H16]  10.67 33.6 90 bottom
R3416  91R3J-GP  [R603H22]  12.12 27.33 180 bottom
R3418  22KR2J-GP  [R402H16]  8.92 19.51 0 bottom
R3419  22KR2J-GP  [R402H16]  10.24 25.37 180 bottom
R3420  2K2R2J-2-GP  [R402H16]  9.96 19.48 0 bottom
R3422  220R5J-GP  [R805H24]  15.19 19.05 0 bottom
R3423  100R5J-4-GP  [R805H24]  6.58 14.53 90 bottom
R3424  100R5J-4-GP  [R805H24]  10.34 12.52 180 top
R3425  100R5J-4-GP  [R805H24]  6.53 10.29 270 top
R3501  1KR2J-1-GP  [R402H16]  183.69 21.34 270 top
R3502  10KR2F-2-GP  [R402H16]  154.69 16.64 0 bottom
R3516  100KR2J-1-GP  [R402H16]  180.42 21.03 180 top
R3517  1KR2J-1-GP  [R402H16]  6.48 93.34 180 bottom
R3518  1KR2J-1-GP  [R402H16]  7.62 93.34 0 bottom
R3519  0R3J-0-U-GP  [R603H22]  185.06 15.15 90 top
R3520  0R3J-0-U-GP  [R603H22]  185.06 16.36 90 top
R3521  100KR2J-1-GP  [R402H16]  152.2 17.07 90 bottom
R3522  10KR2J-3-GP  [R402H16]  155.96 24.36 90 bottom
R3523  2K7R2J-GP  [R402H16]  153.67 16.64 180 bottom
R3524  10KR2J-3-GP  [R402H16]  160.12 22.23 90 bottom
R3525  10KR2F-2-GP  [R402H16]  149.33 21.01 0 top
R3526  10KR2F-2-GP  [R402H16]  148.89 19.51 270 top
R3527  10KR2J-3-GP  [R402H16]  159.72 16.76 90 bottom
R3528  0R0402-PAD-2-GP  [0R0402-PAD-1]  8.15 87.99 90 bottom
R3529  0R2J-2-GP  [R402H16]  59.46 102.92 0 bottom
R3701  10KR2J-3-GP  [R402H16]  32.29 37.85 90 top
R3702  10KR2J-3-GP  [R402H16]  28.42 30.05 180 top
R3703  10KR2J-3-GP  [R402H16]  98.37 151.25 0 top
R3704  10KR2J-3-GP  [R402H16]  62.1 147.27 180 top
R4001  0R2J-2-GP  [R402H16]  74.68 5.33 0 top
R4002  0R2J-2-GP  [R402H16]  73.61 5.33 0 top
R4003  100KR2J-1-GP  [R402H16]  81.41 10.67 180 top
R4004  20KR2J-L2-GP  [R402H16]  96.01 34.8 180 bottom
R4005  4K7R2F-GP  [R402H16]  96.65 37.85 270 bottom
R4006  10KR2F-2-GP  [R402H16]  104.01 37.72 270 bottom
R4301  22KR2J-GP  [R402H16]  168.45 20.12 0 top
R4302  0R0402-PAD-2-GP  [0R0402-PAD-1]  174.32 17.19 180 bottom
R4303  330KR2J-L1-GP  [R402H16]  166.52 22.2 270 top
R4304  100KR2J-1-GP  [R402H16]  168.3 16.15 0 top
R4305  1KR2J-1-GP  [R402H16]  179.96 92.83 180 bottom
R4306  100KR2J-1-GP  [R402H16]  167 20.5 270 top
R4307  4K7R2J-2-GP  [R402H16]  178.94 92.84 0 bottom
R4308  300R5J-GP  [R805H24]  5.46 86.69 0 bottom
R4503  10KR2J-3-GP  [R402H16]  4.83 51.44 0 bottom
R4601  0R0805-PAD-2-GP-U  [0R0805-PAD-1-U]  45.47 107.44 180 bottom
R4602  10KR2J-3-GP  [R402H16]  36.16 104.32 270 bottom
R4603  47KR2J-2-GP  [R402H16]  36.86 103.3 90 bottom
R4604  10KR2J-3-GP  [R402H16]  39.75 106.05 270 bottom
R4605  10KR2J-3-GP  [R402H16]  38.73 107.14 90 bottom
R4606  680R2F-GP  [R402H16]  45.14 95.94 180 bottom
R4607  100KR2J-1-GP  [R402H16]  38.73 108.15 90 bottom
R4608  10KR2J-3-GP  [R402H16]  47.02 107.9 180 bottom
R4609  0R2J-2-GP  [R402H16]  38.94 110.87 0 bottom
R4610  0R2J-2-GP  [R402H16]  37.06 111.99 90 bottom
R4611  30KR2J-4-GP  [R402H16]  43.73 106.85 180 bottom
R4612  30KR2J-4-GP  [R402H16]  37.72 104.8 0 bottom
R4613  30KR2J-4-GP  [R402H16]  42.67 106.87 180 bottom
R4614  30KR2J-4-GP  [R402H16]  41.63 106.87 0 bottom
R5001  10KR2J-3-GP  [R402H16]  81.69 18.72 180 top
R5002  10KR2J-3-GP  [R402H16]  80.64 18.72 180 top
R5003  10KR2J-3-GP  [R402H16]  79.91 14.12 90 top
R5004  0R2J-2-GP  [R402H16]  62.31 103.3 0 top
R5401  10KR2J-3-GP  [R402H16]  161.44 18.92 0 top
R5403  100KR2J-1-GP  [R402H16]  155.45 158.06 270 top
R5601  0R2J-2-GP  [R402H16]  156.59 156 180 bottom
R5602  0R2J-2-GP  [R402H16]  130.45 155.27 0 bottom
R5603  180R2J-1-GP  [R402H16]  139.91 149.63 90 top
R5604  180R2J-1-GP  [R402H16]  143.72 149.66 90 top
R5605  180R2J-1-GP  [R402H16]  147.47 149.68 90 top
R5606  180R2J-1-GP  [R402H16]  151.21 149.73 90 top
R5607  180R2J-1-GP  [R402H16]  111.71 149.43 90 top
R5608  180R2J-1-GP  [R402H16]  115.52 149.45 90 top
R5609  180R2J-1-GP  [R402H16]  119.46 149.45 90 top
R5610  180R2J-1-GP  [R402H16]  123.14 149.4 90 top
R5801  0R3J-0-U-GP  [R603H22]  183.54 141.78 0 bottom
R6101  10KR2J-3-GP  [R402H16]  29.72 72.39 0 top
R6102  10KR2J-3-GP  [R402H16]  29.59 69.8 180 top
R6103  0R0603-PAD-2-GP-U  [0R0603-PAD-1-U]  22.14 57.29 180 top
R6104  0R0402-PAD-2-GP  [0R0402-PAD-1]  28.83 74.42 0 top
R6105  10KR2F-2-GP  [R402H16]  30.86 74.42 0 top
R6106  0R2J-2-GP  [R402H16]  30.86 72.39 0 top
R6107  0R2J-2-GP  [R402H16]  31.06 70.23 90 top
R6108  0R0402-PAD-2-GP  [0R0402-PAD-1]  70.08 84.1 90 top
R6109  0R0402-PAD-2-GP  [0R0402-PAD-1]  70.08 83.06 90 top
R6110  0R2J-2-GP  [R402H16]  31.06 69.19 270 top
R6401  100R2J-2-GP  [R402H14]  9.12 23.52 0 bottom
R6402  100R2J-2-GP  [R402H14]  44.54 68.5 270 top
R6403  100R2J-2-GP  [R402H14]  46.02 68.9 0 top
R6404  10KR2F-2-GP  [R402H16]  81.86 54.2 0 top
R6507  10KR2F-2-GP  [R402H16]  189.53 120.27 0 bottom
R6508  75R2F-2-GP  [R402H16]  92.46 77.67 90 bottom
R6509  75R2F-2-GP  [R402H16]  89.32 75.41 90 bottom
R6510  75R2F-2-GP  [R402H16]  89.65 77.62 90 bottom
R6511  75R2F-2-GP  [R402H16]  88.79 76.48 90 bottom
R6512  75R2F-2-GP  [R402H16]  20.37 148.58 0 top
R6519  10KR2J-3-GP  [R402H16]  90.83 74.17 315 bottom
R6520  10KR2J-3-GP  [R402H16]  9.37 107.19 0 top
R6526  0R2J-2-GP  [R402H16]  22.61 81.92 90 top
R6527  0R2J-2-GP  [R402H16]  91.03 88.95 135 top
R6528  0R2J-2-GP  [R402H16]  114.85 85.29 135 bottom
R6529  0R2J-2-GP  [R402H16]  117.7 89.12 315 bottom
R6532  0R2J-2-GP  [R402H16]  15.62 13.21 0 top
R6533  0R2J-2-GP  [R402H16]  90.3 89.66 135 top
R6534  10KR2J-3-GP  [R402H16]  154.69 159.64 0 top
R6535  10KR2J-3-GP  [R402H16]  136.22 156.9 180 top
R6542  100KR2J-1-GP  [R402H16]  132.43 155.25 0 top
R6556  0R2J-2-GP  [R402H16]  155.83 159.64 180 top
R6557  0R2J-2-GP  [R402H16]  134.7 156.57 90 top
R6558  10KR2J-3-GP  [R402H16]  95.05 140.8 135 top
R6559  10KR2J-3-GP  [R402H16]  91.38 86.13 270 bottom
R6560  49D9R2F-GP  [R402H16]  111.84 98.65 315 bottom
R6561  113R2F-GP  [R402H16]  110.71 109.71 225 top
R6562  0R2J-2-GP  [R402H16]  111.47 110.53 225 top
R6563  402R2F-GP  [R402H16]  109.83 99.29 45 bottom
R6564  10KR2F-2-GP  [R402H16]  15.47 21.39 90 bottom
R6565  10KR2F-2-GP  [R402H16]  13.46 25.02 90 bottom
R6566  10R2J-2-GP  [R402H14]  76.73 44.22 0 top
R6567  33R2J-2-GP  [R402H16]  80.05 60.44 0 top
R6568  10R2J-2-GP  [R402H14]  73.3 44.32 0 top
R6570  10R2J-2-GP  [R402H14]  78.56 60.91 270 top
R6571  10R2J-2-GP  [R402H14]  79.25 44.48 0 top
R6572  10R2J-2-GP  [R402H14]  75.69 60.48 0 top
R6573  2K2R2J-2-GP  [R402H16]  35.1 134.9 0 bottom
R6574  10KR2J-3-GP  [R402H16]  91.59 73.43 315 bottom
R6801  0R0402-PAD-2-GP  [0R0402-PAD-1]  71.42 33.68 0 top
R6802  0R0402-PAD-2-GP  [0R0402-PAD-1]  69.95 29.34 90 top
R6803  0R2J-2-GP  [R402H16]  71.42 31.75 180 top
R6804  0R2J-2-GP  [R402H16]  71.42 29.79 0 top
R9604  1KR2J-1-GP  [R402H16]  177.83 104.14 270 bottom
R9605  0R0402-PAD-2-GP  [0R0402-PAD-1]  177.83 105.28 270 bottom
R9606  10KR2J-3-GP  [R402H16]  176.43 108 270 bottom
R9607  1KR2J-1-GP  [R402H16]  191.74 107.42 270 bottom
R9608  0R0402-PAD-2-GP  [0R0402-PAD-1]  177.93 109.98 270 bottom
R9611  10KR2J-3-GP  [R402H16]  191.23 116.22 270 bottom
R9613  0R0402-PAD-2-GP  [0R0402-PAD-1]  191.74 108.43 270 bottom
R9620  51R2J-2-GP  [R402H16]  190.75 96.14 90 bottom
R9621  0R0402-PAD-2-GP  [0R0402-PAD-1]  190.75 95 270 bottom
R9622  0R0402-PAD-2-GP  [0R0402-PAD-1]  190.55 115.19 90 bottom
R9628  0R0402-PAD-2-GP  [0R0402-PAD-1]  8.51 113.41 0 bottom
R9629  0R0402-PAD-2-GP  [0R0402-PAD-1]  21.72 124.21 0 top
R9643  10KR2J-3-GP  [R402H16]  137.79 150.72 270 top
R9644  0R3J-0-U-GP  [R603H22]  167.41 144.53 180 top
R9645  0R2J-2-GP  [R402H16]  180.16 143.74 90 top
R9647  12KR2J-L-GP  [R402H16]  172.92 142.52 180 top
R9648  4K7R2F-GP  [R402H16]  169.8 149.35 0 top
R9649  4K7R2F-GP  [R402H16]  168.78 149.35 180 top
R9650  4K7R2F-GP  [R402H16]  185.62 144.78 0 bottom
R9651  4K7R2F-GP  [R402H16]  185.6 152.78 180 bottom
R9652  4K7R2F-GP  [R402H16]  184.61 144.78 180 bottom
R9653  4K7R2F-GP  [R402H16]  184.58 152.78 0 bottom
R9654  4K7R2F-GP  [R402H16]  162.33 144.02 0 top
R9655  4K7R2F-GP  [R402H16]  163.4 144.02 180 top
R9656  4K7R2F-GP  [R402H16]  166.27 144.65 180 top
R9657  4K7R2F-GP  [R402H16]  164.49 144.02 180 top
R9658  36R2J-GP  [R402H16]  180.21 152.53 270 top
R9659  36R2J-GP  [R402H16]  180.21 150.5 270 top
R9660  1KR2J-1-GP  [R402H16]  85.24 59.82 315 bottom
R9661  2K2R2J-2-GP  [R402H16]  176.6 69.16 0 bottom
R9662  1KR2J-1-GP  [R402H16]  84.45 60.55 315 bottom
R9663  2K2R2J-2-GP  [R402H16]  174.5 67.06 90 bottom
R9664  2K2R2J-2-GP  [R402H16]  172.95 64.77 0 bottom
R9671  1KR2J-1-GP  [R402H16]  92.84 80.26 270 top
R9672  1KR2J-1-GP  [R402H16]  93.75 97.1 225 top
R9674  20KR2J-L2-GP  [R402H16]  95.35 96.95 225 top
R9675  10KR2J-3-GP  [R402H16]  97.59 82.63 270 top
R9681  470R2F-GP  [R402H16]  146.61 148.59 270 top
R9682  470R2F-GP  [R402H16]  148.51 148.59 90 top
R9683  470R2F-GP  [R402H16]  142.75 148.62 270 top
R9684  470R2F-GP  [R402H16]  144.65 148.62 90 top
R9685  470R2F-GP  [R402H16]  138.91 148.62 270 top
R9686  470R2F-GP  [R402H16]  140.82 148.62 90 top
R9687  470R2F-GP  [R402H16]  150.5 148.56 270 top
R9688  470R2F-GP  [R402H16]  152.53 148.56 90 top
R9689  2KR2J-1-GP  [R402H16]  127 153.16 270 top
R9690  2KR2J-1-GP  [R402H16]  130.33 155.24 0 top
R9691  470R2F-GP  [R402H16]  120.35 148.36 90 top
R9692  470R2F-GP  [R402H16]  118.44 148.36 270 top
R9693  470R2F-GP  [R402H16]  114.53 148.41 270 top
R9694  470R2F-GP  [R402H16]  116.43 148.41 90 top
R9695  470R2F-GP  [R402H16]  110.67 148.41 270 top
R9696  470R2F-GP  [R402H16]  122.3 148.34 270 top
R9697  470R2F-GP  [R402H16]  112.57 148.41 90 top
R9698  470R2F-GP  [R402H16]  124.21 148.34 90 top
R9699  0R0603-PAD-2-GP-U  [0R0603-PAD-1-U]  158.62 160.4 0 top
R9702  100KR2J-1-GP  [R402H16]  180.16 144.83 90 top
R9703  0R0402-PAD-2-GP  [0R0402-PAD-1]  161.04 149.22 0 top
R9704  0R2J-2-GP  [R402H16]  137.79 151.82 90 top
R9705  0R5J-5-GP  [R805H24]  28.83 32.79 0 top
R9707  33R2J-2-GP  [R402H16]  94.87 83.44 90 top
R9708  0R0402-PAD-2-GP  [0R0402-PAD-1]  101.73 35.03 0 bottom
R9709  0R0402-PAD-2-GP  [0R0402-PAD-1]  111.86 35.89 180 bottom
R9723  0R5J-6-GP  [R805H24]  6.83 107.47 270 bottom
R9724  0R5J-6-GP  [R805H24]  6.83 105.44 270 bottom
R9725  10KR2J-3-GP  [R402H16]  63.49 122.77 90 bottom
R9728  0R0402-PAD-2-GP  [0R0402-PAD-1]  60.99 101.19 270 bottom
R9729  0R0402-PAD-2-GP  [0R0402-PAD-1]  53.72 47.88 180 top
R9730  0R2J-2-GP  [R402H16]  52.58 47.88 180 top
